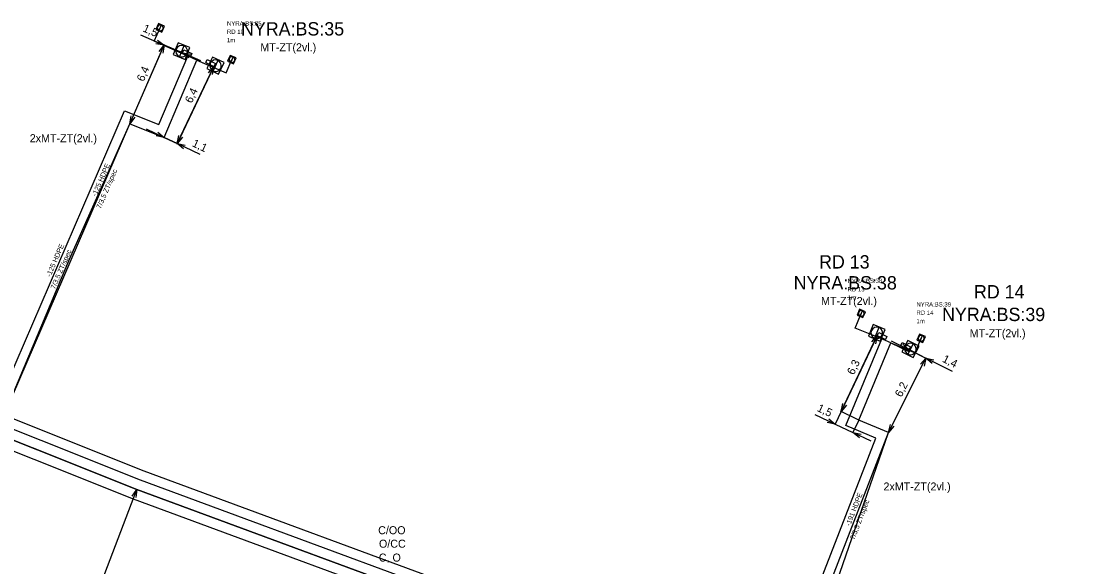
# Model space of a CAD drawing. Extents: x -836739 to -834468, y -1071001 to -1070126.
# Drawn here: x -836340.8 to -836261.8, y -1070401.3 to -1070360.3 of the extents above; entities that cross this region are included whole.
import ezdxf

# ---------------------------------------------------------------- set-up
doc = ezdxf.new("R2010")
doc.units = 0
for name, color, linetype in [('f002_inz_linie_mimo_CETIN', 7, 'Continuous'), ('f003_opt_sit_texty', 7, 'Continuous'), ('f003_opt_sit_znacky', 7, 'Continuous'), ('f006_osa_trasy', 7, 'Continuous'), ('f006_stp_koty', 7, 'Continuous'), ('f309_rozvadec_opt', 7, 'Continuous'), ('f309_rozvadec_opt_ann', 7, 'Continuous'), ('f309_trubicka', 7, 'Continuous'), ('f309_trubicka_ann', 7, 'Continuous'), ('f309_trubka', 7, 'Continuous')]:
    doc.layers.add(name, color=color, linetype=linetype)

msp = doc.modelspace()

# ---------------------------------------------------------------- linework, layer by layer
at = {"layer": 'f002_inz_linie_mimo_CETIN'}
for points in [[(-836328.73, -1070362.74), (-836328.63, -1070362.51), (-836328.03, -1070362.77), (-836328.13, -1070363)], [(-836328.73, -1070362.74), (-836328.63, -1070362.51), (-836328.03, -1070362.77), (-836328.13, -1070363)], [(-836328.73, -1070362.74), (-836328.13, -1070363)], [(-836328.73, -1070362.74), (-836328.13, -1070363)], [(-836326.98, -1070363.46), (-836326.87, -1070363.23), (-836326.26, -1070363.52), (-836326.37, -1070363.75)], [(-836326.98, -1070363.46), (-836326.87, -1070363.23), (-836326.26, -1070363.52), (-836326.37, -1070363.75)], [(-836326.98, -1070363.46), (-836326.37, -1070363.75)], [(-836326.98, -1070363.46), (-836326.37, -1070363.75)], [(-836276.66, -1070383.93), (-836276.55, -1070383.7), (-836275.94, -1070383.99), (-836276.05, -1070384.22)], [(-836276.66, -1070383.93), (-836276.55, -1070383.7), (-836275.94, -1070383.99), (-836276.05, -1070384.22)], [(-836276.66, -1070383.93), (-836276.05, -1070384.22)], [(-836276.66, -1070383.93), (-836276.05, -1070384.22)], [(-836274.9, -1070384.67), (-836274.79, -1070384.45), (-836274.17, -1070384.76), (-836274.28, -1070384.98)], [(-836274.9, -1070384.67), (-836274.79, -1070384.45), (-836274.17, -1070384.76), (-836274.28, -1070384.98)], [(-836274.9, -1070384.67), (-836274.28, -1070384.98)], [(-836274.9, -1070384.67), (-836274.28, -1070384.98)]]:
    msp.add_lwpolyline(points, dxfattribs=at)
at = {"layer": 'f003_opt_sit_znacky'}
for p, q in [((-836328.628, -1070362.2), (-836328.952, -1070363)), ((-836328.628, -1070362.201), (-836328.628, -1070362.2)), ((-836326.063, -1070363.301), (-836326.437, -1070364.079)), ((-836326.063, -1070363.301), (-836326.063, -1070363.301)), ((-836276.535, -1070383.321), (-836276.865, -1070384.119)), ((-836276.535, -1070383.322), (-836276.535, -1070383.321)), ((-836273.97, -1070384.547), (-836274.37, -1070385.313)), ((-836273.971, -1070384.548), (-836273.97, -1070384.547))]:
    msp.add_line(p, q, dxfattribs=at)
for points in [[(-836329.413, -1070362.865), (-836328.523, -1070363.226), (-836328.163, -1070362.336), (-836329.052, -1070361.976)], [(-836326.888, -1070363.916), (-836326.023, -1070364.332), (-836325.607, -1070363.466), (-836326.473, -1070363.051)], [(-836277.325, -1070383.981), (-836276.438, -1070384.348), (-836276.071, -1070383.461), (-836276.957, -1070383.094)], [(-836274.815, -1070385.135), (-836273.964, -1070385.579), (-836273.52, -1070384.728), (-836274.371, -1070384.284)]]:
    msp.add_lwpolyline(points, close=True, dxfattribs=at)
for centre, start, end in [((-836328.787, -1070362.601), 68.2959, 247.5683), ((-836328.787, -1070362.602), 247.52755, 68.33579), ((-836326.248, -1070363.691), 64.72279, 243.9952), ((-836326.247, -1070363.692), 243.95445, 64.76268), ((-836276.697, -1070383.721), 67.86027, 247.13267), ((-836276.697, -1070383.722), 247.09192, 67.90016), ((-836274.168, -1070384.931), 62.81099, 242.08339), ((-836274.168, -1070384.932), 242.04264, 62.85088)]:
    msp.add_arc(centre, 0.432, start, end, dxfattribs=at)
at = {"layer": 'f006_osa_trasy'}
for points in [[(-836259.51, -1070422.49), (-836273.33, -1070418.13), (-836279.63, -1070415.33), (-836305.65, -1070405.26), (-836332.15, -1070395.46), (-836355.51, -1070386.15), (-836363.32, -1070381.37), (-836370.68, -1070374.62), (-836386.63, -1070361.4), (-836412.6, -1070344.19), (-836444.52, -1070318.16), (-836450.35, -1070293.64), (-836451.12, -1070284.95), (-836453.47, -1070277.02), (-836456.68, -1070270.62)], [(-836327.64, -1070363.27), (-836328.85, -1070362.74), (-836328.79, -1070362.6)], [(-836350.1, -1070406.54), (-836348.82, -1070405.5), (-836341.98, -1070389.64), (-836337.19, -1070378.21), (-836332.66, -1070368.05), (-836330.1, -1070369.07), (-836327.64, -1070363.27)], [(-836327.64, -1070363.27), (-836326.33, -1070363.85), (-836326.25, -1070363.69)], [(-836275.63, -1070384.47), (-836276.78, -1070383.96), (-836276.7, -1070383.72)], [(-836289.45, -1070430.62), (-836275.81, -1070391.2), (-836278.03, -1070390.26), (-836275.63, -1070384.47)], [(-836275.63, -1070384.47), (-836274.28, -1070385.12), (-836274.17, -1070384.93)]]:
    msp.add_lwpolyline(points, dxfattribs=at)
at = {"layer": 'f006_stp_koty'}
for p, q in [((-836331.867, -1070361.381), (-836330.101, -1070362.146)), ((-836332.66, -1070368.05), (-836330.101, -1070362.146)), ((-836332.636, -1070367.995), (-836330.078, -1070362.091)), ((-836328.785, -1070362.716), (-836330.157, -1070362.122)), ((-836328.73, -1070362.74), (-836330.101, -1070362.146)), ((-836327.354, -1070363.336), (-836328.73, -1070362.74)), ((-836326.396, -1070363.804), (-836329.146, -1070369.59)), ((-836329.121, -1070369.536), (-836326.37, -1070363.75)), ((-836331.455, -1070368.426), (-836330.1, -1070369.07)), ((-836329.121, -1070369.536), (-836330.1, -1070369.07)), ((-836330.046, -1070369.096), (-836329.066, -1070369.561)), ((-836327.394, -1070370.357), (-836329.121, -1070369.536)), ((-836276.686, -1070383.984), (-836279.839, -1070390.617)), ((-836279.367, -1070389.624), (-836276.66, -1070383.93)), ((-836275.622, -1070384.309), (-836274.28, -1070384.98)), ((-836274.28, -1070384.98), (-836273.016, -1070385.612)), ((-836274.226, -1070385.007), (-836272.962, -1070385.639)), ((-836275.81, -1070391.2), (-836273.016, -1070385.612)), ((-836275.783, -1070391.146), (-836272.989, -1070385.558)), ((-836271.009, -1070386.616), (-836273.016, -1070385.612)), ((-836281.346, -1070389.834), (-836279.813, -1070390.563)), ((-836278.084, -1070390.234), (-836279.421, -1070389.599)), ((-836279.813, -1070390.563), (-836278.476, -1070391.199)), ((-836278.056, -1070390.314), (-836278.502, -1070391.253)), ((-836277.121, -1070391.843), (-836278.476, -1070391.199))]:
    msp.add_line(p, q, dxfattribs=at)
for points in [[(-836330.592, -1070361.769), (-836330.101, -1070362.146), (-836330.712, -1070362.045)], [(-836330.478, -1070362.637), (-836330.101, -1070362.146), (-836330.202, -1070362.756)], [(-836328.239, -1070363.116), (-836328.73, -1070362.74), (-836328.12, -1070362.841)], [(-836326.763, -1070364.227), (-836326.37, -1070363.75), (-836326.492, -1070364.356)], [(-836332.284, -1070367.559), (-836332.66, -1070368.05), (-836332.559, -1070367.44)], [(-836330.577, -1070368.677), (-836330.1, -1070369.07), (-836330.706, -1070368.948)], [(-836328.727, -1070369.058), (-836329.121, -1070369.536), (-836328.998, -1070368.929)], [(-836328.643, -1070369.929), (-836329.121, -1070369.536), (-836328.514, -1070369.658)], [(-836277.053, -1070384.407), (-836276.66, -1070383.93), (-836276.782, -1070384.536)], [(-836274.75, -1070384.578), (-836274.28, -1070384.98), (-836274.884, -1070384.846)], [(-836273.418, -1070386.082), (-836273.016, -1070385.612), (-836273.15, -1070386.216)], [(-836272.546, -1070386.014), (-836273.016, -1070385.612), (-836272.412, -1070385.746)], [(-836278.974, -1070389.147), (-836279.367, -1070389.624), (-836279.245, -1070389.018)], [(-836280.291, -1070390.17), (-836279.813, -1070390.563), (-836280.42, -1070390.441)], [(-836275.408, -1070390.73), (-836275.81, -1070391.2), (-836275.676, -1070390.596)], [(-836277.999, -1070391.592), (-836278.476, -1070391.199), (-836277.87, -1070391.321)], [(-836340.268, -1070416.773), (-836332.149, -1070395.46)], [(-836332.502, -1070395.967), (-836332.149, -1070395.46), (-836332.222, -1070396.074)]]:
    msp.add_lwpolyline(points, dxfattribs=at)
at = {"layer": 'f309_rozvadec_opt'}
for p, q in [((-836330.311, -1070360.661), (-836330.486, -1070361.056)), ((-836330.311, -1070360.661), (-836330.311, -1070360.661)), ((-836324.936, -1070363.041), (-836325.111, -1070363.436)), ((-836324.936, -1070363.041), (-836324.936, -1070363.041)), ((-836277.777, -1070382.069), (-836277.942, -1070382.468)), ((-836277.777, -1070382.069), (-836277.777, -1070382.069)), ((-836273.287, -1070383.93), (-836273.45, -1070384.331)), ((-836273.287, -1070383.931), (-836273.287, -1070383.93))]:
    msp.add_line(p, q, dxfattribs=at)
for points in [[(-836330.714, -1070360.981), (-836330.275, -1070361.176), (-836330.081, -1070360.737), (-836330.52, -1070360.542)], [(-836325.339, -1070363.361), (-836324.9, -1070363.555), (-836324.706, -1070363.116), (-836325.145, -1070362.922)], [(-836278.172, -1070382.399), (-836277.728, -1070382.583), (-836277.545, -1070382.139), (-836277.988, -1070381.955)], [(-836273.68, -1070384.263), (-836273.235, -1070384.444), (-836273.054, -1070383.999), (-836273.499, -1070383.818)]]:
    msp.add_lwpolyline(points, close=True, dxfattribs=at)
for centre, start, end in [((-836330.397, -1070360.859), 66.48142, 245.75383), ((-836330.397, -1070360.859), 245.71308, 66.52131), ((-836325.022, -1070363.239), 66.50825, 245.78066), ((-836325.022, -1070363.239), 245.73991, 66.54815), ((-836277.858, -1070382.269), 67.84104, 247.11345), ((-836277.858, -1070382.269), 247.0727, 67.88094), ((-836273.367, -1070384.131), 68.21077, 247.48318), ((-836273.367, -1070384.131), 247.44243, 68.25067)]:
    msp.add_arc(centre, 0.216, start, end, dxfattribs=at)
at = {"layer": 'f309_trubicka'}
for points in [[(-836400.273, -1070369.489), (-836391.917, -1070372.915), (-836392.98, -1070376.276), (-836393.807, -1070378.894), (-836377.072, -1070387.864), (-836347.119, -1070398.841), (-836346.84, -1070398.955), (-836333.059, -1070367.084), (-836330.504, -1070368.102), (-836328.325, -1070362.967), (-836330.838, -1070361.855), (-836330.397, -1070360.859)], [(-836400.273, -1070369.489), (-836392.632, -1070372.689), (-836393.695, -1070376.05), (-836394.709, -1070379.261), (-836377.38, -1070388.55), (-836347.39, -1070399.54), (-836346.443, -1070399.927), (-836332.66, -1070368.05), (-836330.1, -1070369.07), (-836327.64, -1070363.27), (-836325.462, -1070364.234), (-836325.022, -1070363.239)], [(-836400.273, -1070369.489), (-836394.777, -1070372.011), (-836395.84, -1070375.372), (-836397.495, -1070380.612), (-836395.663, -1070381.302), (-836378.304, -1070390.608), (-836348.203, -1070401.64), (-836289.959, -1070425.398), (-836287.821, -1070420.156), (-836276.772, -1070391.607), (-836279.008, -1070390.66), (-836276.322, -1070384.183), (-836278.31, -1070383.359), (-836277.858, -1070382.269)], [(-836400.273, -1070369.489), (-836395.493, -1070371.785), (-836396.555, -1070375.146), (-836398.424, -1070381.064), (-836395.974, -1070381.986), (-836378.612, -1070391.294), (-836348.474, -1070402.34), (-836289.548, -1070426.376), (-836287.124, -1070420.433), (-836275.81, -1070391.2), (-836278.03, -1070390.26), (-836275.63, -1070384.47), (-836273.812, -1070385.224), (-836273.367, -1070384.131)]]:
    msp.add_lwpolyline(points, dxfattribs=at)
at = {"layer": 'f309_trubka'}
for points in [[(-836456.329, -1070272.991), (-836454.17, -1070277.297), (-836451.86, -1070285.091), (-836451.092, -1070293.76), (-836445.25, -1070318.333), (-836412.956, -1070344.122), (-836386.5, -1070361.575), (-836363.141, -1070381.843), (-836355.073, -1070386.347), (-836354.374, -1070386.603), (-836332.15, -1070395.46), (-836305.65, -1070405.26), (-836279.63, -1070415.33), (-836273.33, -1070418.13), (-836262.175, -1070421.648)], [(-836261.299, -1070421.137), (-836273.064, -1070417.427), (-836279.342, -1070414.637), (-836305.385, -1070404.559), (-836331.881, -1070394.76), (-836354.106, -1070385.902), (-836354.759, -1070385.663), (-836362.708, -1070381.226), (-836386.046, -1070360.976), (-836412.515, -1070343.515), (-836444.58, -1070317.908), (-836450.178, -1070294.362), (-836450.35, -1070293.64), (-836451.12, -1070284.95), (-836453.47, -1070277.02), (-836455.659, -1070272.655)], [(-836454.989, -1070272.319), (-836452.77, -1070276.743), (-836450.38, -1070284.809), (-836449.608, -1070293.52), (-836449.436, -1070294.242), (-836443.91, -1070317.483), (-836412.074, -1070342.908), (-836385.592, -1070360.377), (-836362.275, -1070380.609), (-836354.445, -1070384.979), (-836353.838, -1070385.201), (-836331.612, -1070394.06), (-836305.12, -1070403.858), (-836279.054, -1070413.944), (-836272.798, -1070416.724), (-836261.073, -1070420.421)], [(-836457, -1070273.327), (-836454.87, -1070277.574), (-836452.6, -1070285.232), (-836451.834, -1070293.88), (-836451.663, -1070294.602), (-836445.92, -1070318.758), (-836413.397, -1070344.729), (-836386.954, -1070362.174), (-836363.574, -1070382.46), (-836355.387, -1070387.031), (-836354.642, -1070387.304), (-836332.419, -1070396.16), (-836305.915, -1070405.961), (-836279.918, -1070416.023), (-836273.596, -1070418.833), (-836262.401, -1070422.363)]]:
    msp.add_lwpolyline(points, dxfattribs=at)

# ---------------------------------------------------------------- texts
at = {"layer": 'f003_opt_sit_texty'}
for s, height, p in [('NYRA:BS:35', 1, (-836324.34, -1070361.43)), ('MT-ZT(2vl.)', 0.6, (-836322.89, -1070362.61)), ('2xMT-ZT(2vl.)', 0.6, (-836340.17, -1070369.43)), ('RD 13', 1, (-836281.02, -1070378.9)), ('NYRA:BS:38', 1, (-836282.92, -1070380.47)), ('RD 14', 1, (-836269.41, -1070381.14)), ('MT-ZT(2vl.)', 0.6, (-836280.87, -1070381.63)), ('NYRA:BS:39', 1, (-836271.8, -1070382.84)), ('MT-ZT(2vl.)', 0.6, (-836269.73, -1070384.05)), ('2xMT-ZT(2vl.)', 0.6, (-836276.19, -1070395.54)), ('C/OO', 0.6, (-836314.06, -1070398.82)), ('O/CC', 0.6, (-836314, -1070399.83)), ('C, O', 0.6, (-836314.01, -1070400.87))]:
    msp.add_text(s, height=height, dxfattribs=at).set_placement(p)
at = {"layer": 'f006_stp_koty'}
for s, rotation, p in [('1,5', 336.57131, (-836331.748, -1070361.105)), ('6,4', 66.57131, (-836331.635, -1070364.929)), ('6,4', 64.57313, (-836328.035, -1070366.554)), ('1,1', 334.57313, (-836328.05, -1070369.712)), ('6,3', 64.57313, (-836278.415, -1070386.922)), ('1,4', 333.43495, (-836271.834, -1070385.868)), ('6,2', 63.43495, (-836274.84, -1070388.59)), ('1,5', 334.57313, (-836281.217, -1070389.563))]:
    msp.add_text(s, height=0.6, rotation=rotation, dxfattribs=at).set_placement(p)
at = {"layer": 'f309_rozvadec_opt_ann'}
for s, p in [('NYRA:BS:35', (-836325.39, -1070360.688)), ('1m', (-836325.39, -1070361.938)), ('RD 10', (-836325.39, -1070361.312)), ('NYRA:BS:38', (-836278.88, -1070379.988)), ('RD 13', (-836278.88, -1070380.613)), ('1m', (-836278.88, -1070381.238)), ('NYRA:BS:39', (-836273.72, -1070381.748)), ('RD 14', (-836273.72, -1070382.373)), ('1m', (-836273.72, -1070382.998))]:
    msp.add_text(s, height=0.325, dxfattribs=at).set_placement(p)
at = {"layer": 'f309_trubicka_ann'}
for s, rotation, p in [('-125 HDPE', 66.61728, (-836335.191, -1070373.527)), ('7/3,5 ZT/spec', 66.61728, (-836334.857, -1070374.454)), ('-125 HDPE', 66.61638, (-836338.616, -1070379.558)), ('7/3,5 ZT/spec', 66.61638, (-836338.282, -1070380.485)), ('-191 HDPE', 68.84215, (-836278.696, -1070398.241)), ('7/3,5 ZT/spec', 68.84215, (-836278.372, -1070399.273))]:
    msp.add_text(s, height=0.375, rotation=rotation, dxfattribs=at).set_placement(p)

doc.saveas('drawing.dxf')
